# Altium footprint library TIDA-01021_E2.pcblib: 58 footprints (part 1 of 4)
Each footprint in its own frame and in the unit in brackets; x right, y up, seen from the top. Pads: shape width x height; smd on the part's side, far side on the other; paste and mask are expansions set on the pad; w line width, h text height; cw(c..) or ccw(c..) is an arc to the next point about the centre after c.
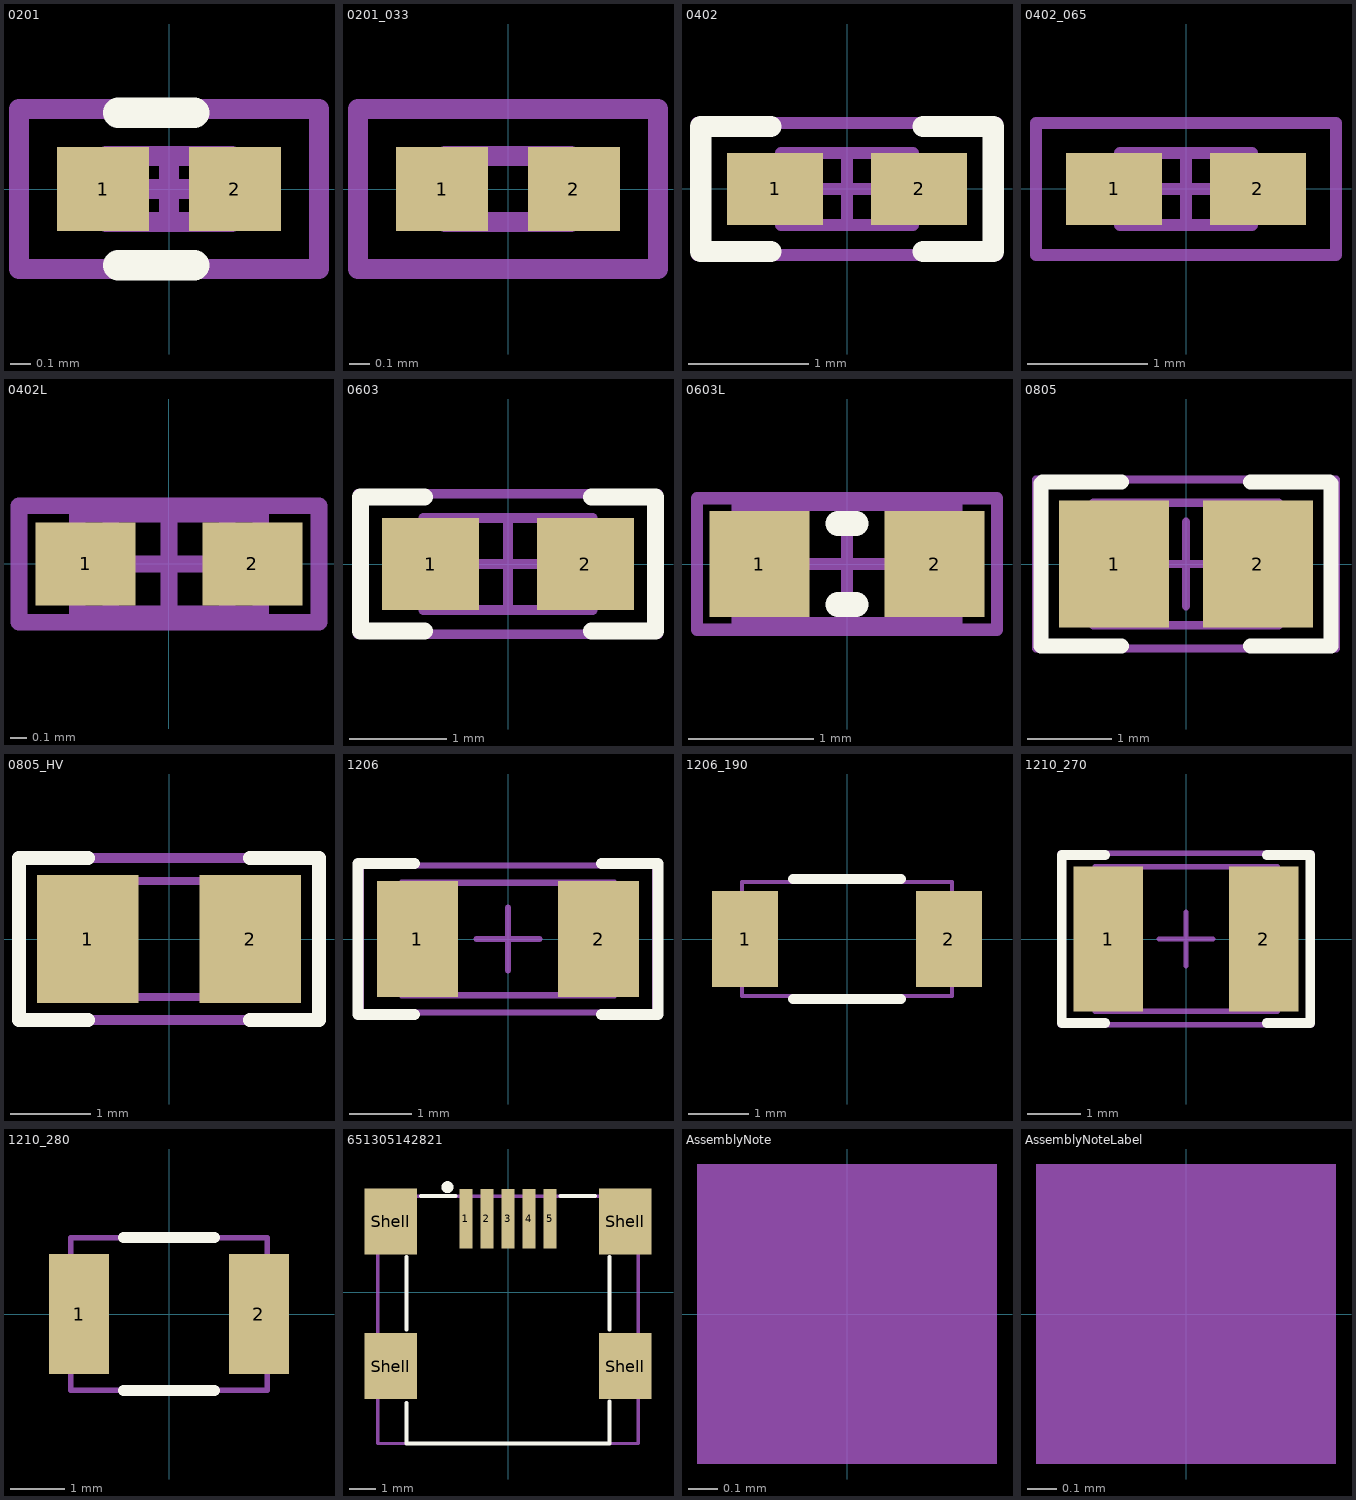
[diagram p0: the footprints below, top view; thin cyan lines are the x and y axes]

## 0201 [mm] "Data from Kemet datasheet CC101_COM dated 7/28/11"
height 0.26
pads (2):
  rect 0.46x0.42 smd mask+0.048: 1(-0.33,0) 2(0.33,0)
Top Overlay:
  lines w0.152: -0.254,-0.381 0.127,-0.381 ; -0.254,0.381 0.127,0.381
Mechanical 5:
  lines w0.1: -0.75,-0.4 0.75,-0.4 0.75,0.4 -0.75,0.4 -0.75,-0.4
  text ".Designator" at -1.026,0.312 h0.64
Mechanical 13:
  lines w0.1: -0.215,-0.165 -0.215,0.165 ; 0.215,-0.165 0.215,0.165 ; -0.315,-0.165 -0.315,0.165 0.315,0.165 0.315,-0.165 -0.315,-0.165
Mechanical 15:
  lines w0.1: -0.165,0 0.165,0 ; 0,-0.165 0,0.165 ; -0.75,-0.4 -0.75,0.4 0.75,0.4 0.75,-0.4 -0.75,-0.4
3D body: height 0.26, standoff 0, extent -0.314,-0.164 -0.216,0.164
3D body: height 0.26, standoff 0, extent -0.214,-0.164 0.214,0.164
3D body: height 0.26, standoff 0, extent 0.216,-0.164 0.314,0.164

## 0201_033 [mm] "SMD, 2-Leads, Height 0.33mm"
height 0.33
pads (2):
  rect 0.46x0.42 smd mask+0.048: 1(-0.33,0) 2(0.33,0)
Mechanical 5:
  lines w0.1: -0.75,-0.4 -0.75,0.4 0.75,0.4 0.75,-0.4 -0.75,-0.4
  text ".Designator" at -2.035,-0.307 h0.64
Mechanical 13:
  lines w0.1: -0.215,-0.165 -0.215,0.165 ; 0.215,-0.165 0.215,0.165 ; -0.315,-0.165 0.315,-0.165 0.315,0.165 -0.315,0.165 -0.315,-0.165
3D body: height 0.33, standoff 0, extent 0.216,-0.164 0.314,0.164
3D body: height 0.33, standoff 0, extent -0.214,-0.164 0.214,0.164
3D body: height 0.33, standoff 0, extent -0.314,-0.164 -0.216,0.164

## 0402 [mm] "0402 from SM-752 data"
height 0.6
pads (2):
  rect 0.8x0.6 smd: 1(-0.6,0) 2(0.6,0)
Top Overlay:
  lines w0.178: -0.635,-0.521 -1.219,-0.521 -1.219,0.521 -0.635,0.521 ; 0.635,-0.521 1.219,-0.521 1.219,0.521 0.635,0.521
Mechanical 5:
  lines w0.1: -1.25,-0.55 -1.25,0.55 1.25,0.55 1.25,-0.55 -1.25,-0.55
  text ".Designator" at -1.117,-0.305 h0.61
Mechanical 13:
  lines w0.1: -0.35,-0.3 -0.35,0.3 ; 0.35,-0.3 0.35,0.3 ; -0.55,-0.3 0.55,-0.3 0.55,0.3 -0.55,0.3 -0.55,-0.3
Mechanical 15:
  lines w0.1: -0.3,0 0.3,0 ; 0,-0.3 0,0.3 ; -1.25,-0.55 1.25,-0.55 1.25,0.55 -1.25,0.55 -1.25,-0.55
3D body: height 0.6, standoff 0, extent 0.351,-0.299 0.549,0.299
3D body: height 0.6, standoff 0, extent -0.349,-0.299 0.349,0.299
3D body: height 0.6, standoff 0, extent -0.549,-0.299 -0.351,0.299

## 0402_065 [mm] "0402"
height 0.65
pads (2):
  rect 0.8x0.6 smd: 1(-0.6,0) 2(0.6,0)
Mechanical 5:
  lines w0.1: -1.25,-0.55 1.25,-0.55 1.25,0.55 -1.25,0.55 -1.25,-0.55
  text ".Designator" at 1.567,-0.378 h0.64
Mechanical 13:
  lines w0.1: -0.35,-0.3 -0.35,0.3 ; -0.55,-0.3 -0.55,0.3 0.55,0.3 0.55,-0.3 -0.55,-0.3
Mechanical 15:
  lines w0.1: -0.3,0 0.3,0 ; 0,-0.3 0,0.3 ; -1.25,-0.55 -1.25,0.55 1.25,0.55 1.25,-0.55 -1.25,-0.55
3D body: height 0.65, standoff 0, extent -0.549,-0.299 -0.351,0.299
3D body: height 0.65, standoff 0, extent -0.349,-0.299 0.349,0.299

## 0402L [mm] "0402 from SM-752 data"
height 0.6
pads (2):
  rect 0.6x0.5 smd: 1(-0.5,0) 2(0.5,0)
Mechanical 5:
  lines w0.1: -0.9,-0.35 -0.9,0.35 0.9,0.35 0.9,-0.35 -0.9,-0.35
  text ".Designator" at 0.79,-0.62 h0.64
Mechanical 13:
  lines w0.1: -0.35,-0.3 -0.35,0.3 ; 0.35,-0.3 0.35,0.3 ; -0.55,-0.3 0.55,-0.3 0.55,0.3 -0.55,0.3 -0.55,-0.3
Mechanical 15:
  lines w0.1: -0.3,0 0.3,0 ; 0,-0.3 0,0.3 ; -0.9,-0.35 0.9,-0.35 0.9,0.35 -0.9,0.35 -0.9,-0.35
3D body: height 0.6, standoff 0, extent 0.351,-0.299 0.549,0.299
3D body: height 0.6, standoff 0, extent -0.349,-0.299 0.349,0.299
3D body: height 0.6, standoff 0, extent -0.549,-0.299 -0.351,0.299

## 0603 [mm] "0603 from SM-752 data"
height 1
pads (2):
  rect 1x0.95 smd: 1(-0.8,0) 2(0.8,0)
Top Overlay:
  lines w0.178: -0.864,-0.691 -1.524,-0.691 -1.524,0.693 -0.864,0.693 ; 0.864,-0.691 1.524,-0.691 1.524,0.693 0.864,0.693
Mechanical 5:
  lines w0.1: -1.55,-0.725 1.55,-0.725 1.55,0.725 -1.55,0.725 -1.55,-0.725
  text ".Designator" at -1.148,-0.285 h0.64
Mechanical 13:
  lines w0.1: -0.55,-0.475 -0.55,0.475 ; 0.55,-0.475 0.55,0.475 ; -0.875,-0.475 -0.875,0.475 0.875,0.475 0.875,-0.475 -0.875,-0.475
Mechanical 15:
  lines w0.1: -0.475,0 0.475,0 ; 0,-0.475 0,0.475 ; -1.55,-0.725 -1.55,0.725 1.55,0.725 1.55,-0.725 -1.55,-0.725
3D body: height 1, standoff 0, extent 0.551,-0.474 0.874,0.474
3D body: height 1, standoff 0, extent -0.549,-0.474 0.549,0.474
3D body: height 1, standoff 0, extent -0.874,-0.474 -0.551,0.474

## 0603L [mm] "0603 from SM-752 data"
height 1
pads (2):
  rect 0.8x0.85 smd: 1(-0.7,0) 2(0.7,0)
Top Overlay:
  lines w0.2: -0.071,-0.325 0.071,-0.325 ; -0.071,0.325 0.071,0.325
Mechanical 5:
  lines w0.1: -1.2,-0.525 -1.2,0.525 1.2,0.525 1.2,-0.525 -1.2,-0.525
  text ".Designator" at -0.795,-0.312 h0.64
Mechanical 13:
  lines w0.1: -0.55,-0.475 -0.55,0.475 ; 0.55,-0.475 0.55,0.475 ; -0.875,-0.475 -0.875,0.475 0.875,0.475 0.875,-0.475 -0.875,-0.475
Mechanical 15:
  lines w0.1: -0.475,0 0.475,0 ; 0,-0.475 0,0.475 ; -1.2,-0.525 1.2,-0.525 1.2,0.525 -1.2,0.525 -1.2,-0.525
3D body: height 1, standoff 0, extent 0.551,-0.474 0.874,0.474
3D body: height 1, standoff 0, extent -0.549,-0.474 0.549,0.474
3D body: height 1, standoff 0, extent -0.874,-0.474 -0.551,0.474

## 0805 [mm] "0805 from SM-752 data"
height 1.45
pads (2):
  rect 1.3x1.5 smd: 1(-0.85,0) 2(0.85,0)
Top Overlay:
  lines w0.178: -0.762,-0.968 -1.717,-0.968 -1.717,0.95 -1.699,0.968 -0.762,0.968 ; 0.762,-0.968 1.717,-0.968 1.717,0.95 1.699,0.968 0.762,0.968
Mechanical 5:
  lines w0.1: -1.775,-1 1.775,-1 1.775,1 -1.775,1 -1.775,-1
  text ".Designator" at 0.676,0.251 h0.64
Mechanical 13:
  lines w0.1: -0.65,-0.725 -0.65,0.725 ; 0.65,-0.725 0.65,0.725 ; -1.1,-0.725 1.1,-0.725 1.1,0.725 -1.1,0.725 -1.1,-0.725
Mechanical 15:
  lines w0.1: -0.5,0 0.5,0 ; 0,-0.5 0,0.5 ; -1.775,-1 1.775,-1 1.775,1 -1.775,1 -1.775,-1
3D body: height 1.45, standoff 0, extent -1.099,-0.724 -0.651,0.724
3D body: height 1.45, standoff 0, extent -0.649,-0.724 0.649,0.724
3D body: height 1.45, standoff 0, extent 0.651,-0.724 1.099,0.724

## 0805_HV [mil] "0805 with 30mil clearance between pads"
height 57.09
pads (2):
  rect 50x63 smd: 1(-40,0) 2(40,0)
Top Overlay:
  lines w7: -40,-40 -74,-40 -74,0 -74,40 -40,40 ; 40,-40 74,-40 74,0 74,40 40,40
Mechanical 5:
  lines w5: -74,-40 -74,40 74,40 74,-40 -74,-40
  text ".Designator" at -44.47,-9.83 h25
Mechanical 13:
  lines w3.94: -25.59,-28.54 -25.59,28.54 ; 25.59,-28.54 25.59,28.54 ; -43.31,-28.54 -43.31,28.54 43.31,28.54 43.31,-28.54 -43.31,-28.54
3D body: height 57.09, standoff 0, extent 25.61,-28.52 43.29,28.52
3D body: height 57.09, standoff 0, extent -25.57,-28.52 25.57,28.52
3D body: height 57.09, standoff 0, extent -43.29,-28.52 -25.61,28.52

## 1206 [mm] "1206 from SM-752 data"
height 1.35
pads (2):
  rect 1.3x1.85 smd: 1(-1.45,0) 2(1.45,0)
Top Overlay:
  lines w0.178: -1.5,-1.21 -2.4,-1.21 -2.4,1.21 -1.5,1.21 ; 1.5,-1.21 2.4,-1.21 2.4,1.21 1.5,1.21
Mechanical 5:
  lines w0.1: -1.7,-0.9 -1.7,0.9 1.7,0.9 1.7,-0.9 -1.7,-0.9
  text ".Designator" at 0.893,0.241 h0.64
Mechanical 13:
  lines w0.1: -1.2,-0.9 -1.2,0.9 ; 1.2,-0.9 1.2,0.9 ; -1.7,-0.9 -1.7,0.9 1.7,0.9 1.7,-0.9 -1.7,-0.9
Mechanical 15:
  lines w0.1: -0.5,0 0.5,0 ; 0,-0.5 0,0.5 ; -2.35,-1.175 -2.35,1.175 2.35,1.175 2.35,-1.175 -2.35,-1.175
3D body: height 1.35, standoff 0, extent 1.201,-0.899 1.699,0.899
3D body: height 1.35, standoff 0, extent -1.199,-0.899 1.199,0.899
3D body: height 1.35, standoff 0, extent -1.699,-0.899 -1.201,0.899

## 1206_190 [mm] "1206_190"
height 1.9
pads (2):
  rect 1.1x1.6 smd: 1(-1.7,0) 2(1.7,0)
Top Overlay:
  lines w0.17: -0.9,-1 0.9,-1 ; -0.9,1 0.9,1
Mechanical 5:
  lines w0.07: -1.75,-0.95 1.75,-0.95 1.75,0.95 -1.75,0.95 -1.75,-0.95
  text ".Designator" at 0.762,0.279 h0.64
3D body: height 1.9, standoff 0, extent -1.749,-0.949 -1.301,0.949
3D body: height 1.9, standoff 0, extent -1.299,-0.949 1.299,0.949
3D body: height 1.9, standoff 0, extent 1.301,-0.949 1.749,0.949

## 1210_270 [mm] "1210"
height 2.7
pads (2):
  rect 1.3x2.7 smd: 1(-1.45,0) 2(1.45,0)
Top Overlay:
  lines w0.178: -1.511,-1.568 -2.316,-1.568 -2.316,1.568 -1.511,1.568 ; 1.511,-1.568 2.316,-1.568 2.316,1.568 1.511,1.568
Mechanical 5:
  lines w0.1: -1.7,-1.35 1.7,-1.35 1.7,1.35 -1.7,1.35 -1.7,-1.35
  text ".Designator" at 1.011,0.207 h0.64
Mechanical 13:
  lines w0.1: -1.2,-1.35 -1.2,1.35 ; 1.2,-1.35 1.2,1.35 ; -1.7,-1.35 -1.7,1.35 1.7,1.35 1.7,-1.35 -1.7,-1.35
Mechanical 15:
  lines w0.1: -0.5,0 0.5,0 ; 0,-0.5 0,0.5 ; -2.35,-1.6 -2.35,1.6 2.35,1.6 2.35,-1.6 -2.35,-1.6
3D body: height 2.7, standoff 0, extent -1.699,-1.349 -1.201,1.349
3D body: height 2.7, standoff 0, extent -1.199,-1.349 1.199,1.349
3D body: height 2.7, standoff 0, extent 1.201,-1.349 1.699,1.349

## 1210_280 [mm] "SMD, 2-Leads, Body 3.6x2.8mm, Height 2.8mm"
height 2.8
pads (2):
  rect 1.1x2.2 smd: 1(-1.65,0) 2(1.65,0)
Top Overlay:
  lines w0.2: -0.835,-1.4 0.835,-1.4 ; -0.835,1.4 0.835,1.4
Mechanical 5:
  lines w0.1: -1.8,-1.4 1.8,-1.4 1.8,1.4 -1.8,1.4 -1.8,-1.4
  text ".Designator" at -0.942,-0.397 h0.64
3D body: height 2.8, standoff 0, extent 1.6,-1.4 1.8,1.4
3D body: height 2.8, standoff 0, extent -1.6,-1.4 1.6,1.4
3D body: height 2.8, standoff 0, extent -1.8,-1.4 -1.6,1.4

## 651305142821 [mm] "5 pins"
height 4
pads (9):
  rect 0.5x2.25 smd: 1(-1.6,2.8) 2(-0.8,2.8) 3(0,2.8) 4(0.8,2.8) 5(1.6,2.8)
  rect 2x2.5 smd: Shell(-4.45,-2.8) Shell(-4.45,2.7) Shell(4.45,-2.8) Shell(4.45,2.7)
Top Overlay:
  circle w0.254: c-2.3,4 r0.1
  lines w0.152: -3.85,-4.2 -3.85,-5.74 3.85,-5.74 ; -3.85,-1.4 -3.85,1.35 ; -3.3,3.66 -1.99,3.66 ; 2,3.66 3.3,3.66 ; 3.85,-5.74 3.85,-4.15 ; 3.85,-1.4 3.85,1.35
Mechanical 13:
  lines w0.127: -4.95,-5.74 4.95,-5.74 4.95,3.66 -4.95,3.66 -4.95,-5.74
3D body "651305142821.stp": height -0.4, standoff -4.5, extent -4.95,-5.74 4.95,3.66

## AssemblyNote [mm] "Assembly Note"
Mechanical 5:
  rectangle: -0.508,-0.508 0.508,0.508
  text ".Designator" at -4.191,-0.508 h0.64
  text ".Comment" at 1.143,-0.508 h0.64

## AssemblyNoteLabel [mm] "Assembly Note for PCB Labels"
Mechanical 5:
  rectangle: -0.508,-0.508 0.508,0.508
  text ".Designator" at -4.191,-0.508 h0.64
  text "Install label in silkscreened box after final wash.  Text shall be 8 pt font.  Text shall be per the Label Table in the PDF schematic." at 1.143,-0.508 h0.64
